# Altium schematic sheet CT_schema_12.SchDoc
size 281 x 153 mm
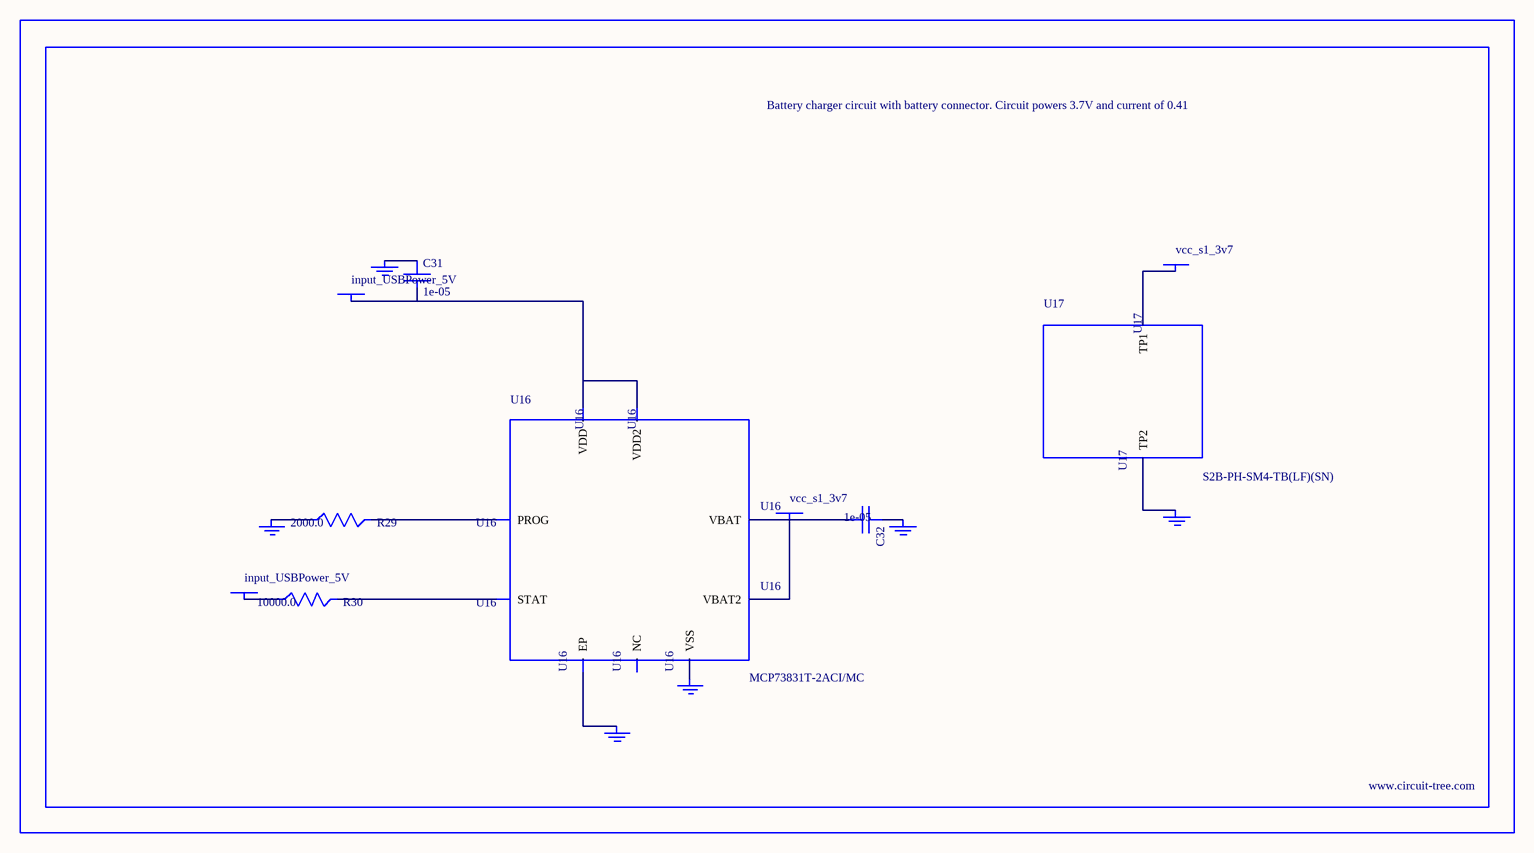
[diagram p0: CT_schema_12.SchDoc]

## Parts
BORDER11  (no value)
C31  1e-05  [C1206]
C32  1e-05  [C1206]
GND_INSTANCE_11_0  (no value)
GND_INSTANCE_11_1  (no value)
GND_INSTANCE_11_2  (no value)
GND_INSTANCE_11_3  (no value)
GND_INSTANCE_11_4  (no value)
GND_INSTANCE_11_5  (no value)
POWER_INSTANCE_11_0  input_USBPower_5V
POWER_INSTANCE_11_1  input_USBPower_5V
POWER_INSTANCE_11_2  vcc_s1_3v7
POWER_INSTANCE_11_3  vcc_s1_3v7
R29  2000.0  [R0603]
R30  10000.0  [R0603]
U16  MCP73831T-2ACI/MC  [DFN8_2X3MC]
U17  S2B-PH-SM4-TB(LF)(SN)  [JST-2-SMD]

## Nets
NetC31_1: C31.1 GND_INSTANCE_11_0.0(GND)
NetC31_2: C31.2 POWER_INSTANCE_11_0.0(PWR) U16.1(VDD) U16.2(VDD2)
NetC32_1: C32.1 GND_INSTANCE_11_1.0(GND)
NetC32_2: C32.2 POWER_INSTANCE_11_2.0(PWR) U16.3(VBAT) U16.4(VBAT2)
NetGND_INSTANCE_11_2_0: GND_INSTANCE_11_2.0(GND) R29.1
NetGND_INSTANCE_11_3_0: GND_INSTANCE_11_3.0(GND) U16.9(EP)
NetGND_INSTANCE_11_4_0: GND_INSTANCE_11_4.0(GND) U16.6(VSS)
NetGND_INSTANCE_11_5_0: GND_INSTANCE_11_5.0(GND) U17.2(TP2)
NetPOWER_INSTANCE_11_1_0: POWER_INSTANCE_11_1.0(PWR) R30.1
NetPOWER_INSTANCE_11_3_0: POWER_INSTANCE_11_3.0(PWR) U17.1(TP1)
NetR29_2: R29.2 U16.8(PROG)
NetR30_2: R30.2 U16.5(STAT)

Not connected (* = marked no-connect by the designer): U16 7(NC)

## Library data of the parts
BORDER11 = BORDER_PAGE11
C31 C32 = C1206C106K3RACTU
GND_INSTANCE_11_0-GND_INSTANCE_11_5 = GND
POWER_INSTANCE_11_0-POWER_INSTANCE_11_3 = PWR
R29 = RC0603JR-072KL
R30 = RC0603JR-0710KL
